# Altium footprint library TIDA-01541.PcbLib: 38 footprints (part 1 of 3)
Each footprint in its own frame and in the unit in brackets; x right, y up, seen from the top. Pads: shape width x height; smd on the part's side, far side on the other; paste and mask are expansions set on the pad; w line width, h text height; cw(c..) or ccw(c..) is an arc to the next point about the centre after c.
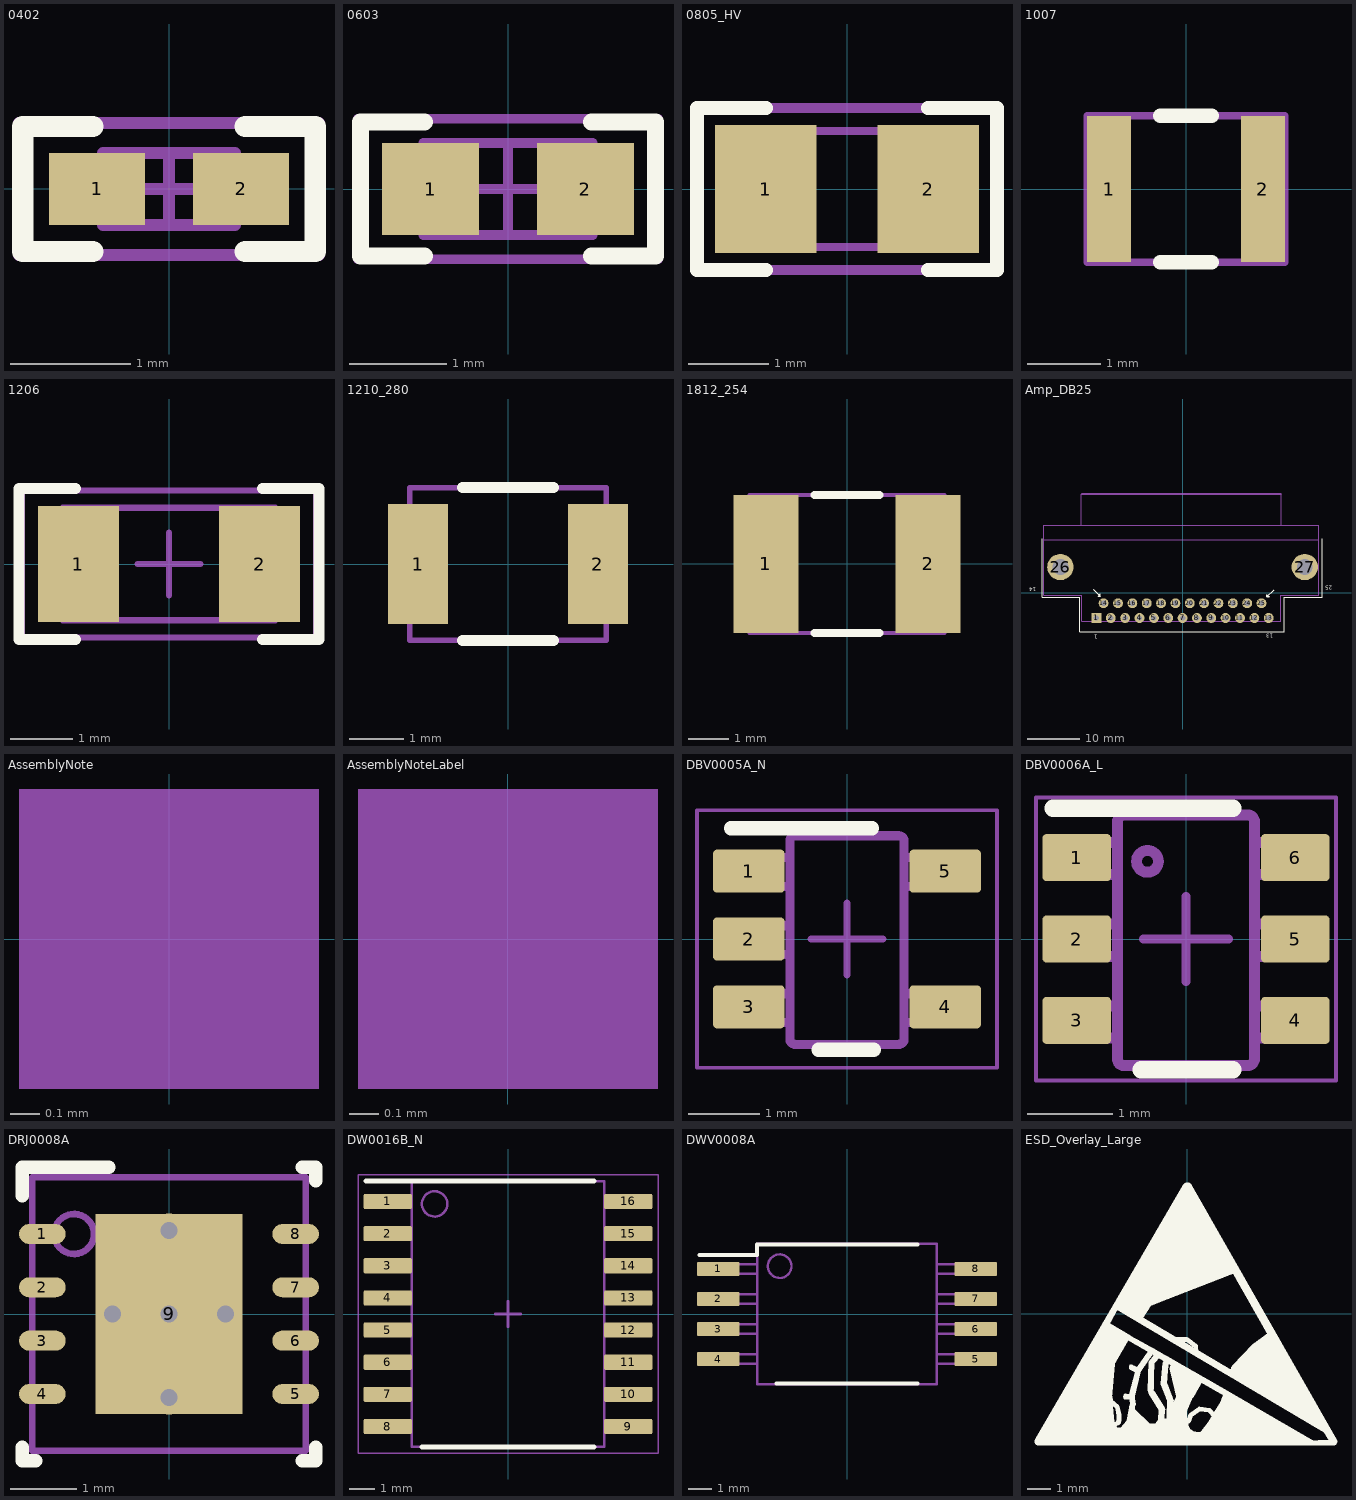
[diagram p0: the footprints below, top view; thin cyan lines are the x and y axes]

## 0402 [mm] "0402 from SM-752 data"
height 0.6
pads (2):
  rect 0.8x0.6 smd: 1(-0.6,0) 2(0.6,0)
Top Overlay:
  lines w0.178: -0.635,-0.521 -1.219,-0.521 -1.219,0.521 -0.635,0.521 ; 0.635,-0.521 1.219,-0.521 1.219,0.521 0.635,0.521
Mechanical 5:
  lines w0.1: -1.25,-0.55 -1.25,0.55 1.25,0.55 1.25,-0.55 -1.25,-0.55
  text ".Designator" at -1.6,0.305 h0.76
Mechanical 13:
  lines w0.1: -0.35,-0.3 -0.35,0.3 ; 0.35,-0.3 0.35,0.3 ; -0.55,-0.3 0.55,-0.3 0.55,0.3 -0.55,0.3 -0.55,-0.3
Mechanical 15:
  lines w0.1: -0.3,0 0.3,0 ; 0,-0.3 0,0.3 ; -1.25,-0.55 1.25,-0.55 1.25,0.55 -1.25,0.55 -1.25,-0.55
3D body: height 0.6, standoff 0, extent 0.351,-0.299 0.549,0.299
3D body: height 0.6, standoff 0, extent -0.349,-0.299 0.349,0.299
3D body: height 0.6, standoff 0, extent -0.549,-0.299 -0.351,0.299

## 0603 [mm] "0603 from SM-752 data"
height 1
pads (2):
  rect 1x0.95 smd: 1(-0.8,0) 2(0.8,0)
Top Overlay:
  lines w0.178: -0.864,-0.691 -1.524,-0.691 -1.524,0.693 -0.864,0.693 ; 0.864,-0.691 1.524,-0.691 1.524,0.693 0.864,0.693
Mechanical 5:
  lines w0.1: -1.55,-0.725 1.55,-0.725 1.55,0.725 -1.55,0.725 -1.55,-0.725
  text ".Designator" at -1.397,-0.381 h0.76
Mechanical 13:
  lines w0.1: -0.55,-0.475 -0.55,0.475 ; 0.55,-0.475 0.55,0.475 ; -0.875,-0.475 -0.875,0.475 0.875,0.475 0.875,-0.475 -0.875,-0.475
Mechanical 15:
  lines w0.1: -0.475,0 0.475,0 ; 0,-0.475 0,0.475 ; -1.55,-0.725 -1.55,0.725 1.55,0.725 1.55,-0.725 -1.55,-0.725
3D body: height 1, standoff 0, extent 0.551,-0.474 0.874,0.474
3D body: height 1, standoff 0, extent -0.549,-0.474 0.549,0.474
3D body: height 1, standoff 0, extent -0.874,-0.474 -0.551,0.474

## 0805_HV [mil] "0805 with 30mil clearance between pads"
height 57.09
pads (2):
  rect 50x63 smd: 1(-40,0) 2(40,0)
Top Overlay:
  lines w7: -40,-40 -74,-40 -74,0 -74,40 -40,40 ; 40,-40 74,-40 74,0 74,40 40,40
Mechanical 5:
  lines w5: -74,-40 74,-40 74,40 -74,40 -74,-40
  text ".Designator" at 39,13 h30
Mechanical 13:
  lines w3.94: -25.59,-28.54 -25.59,28.54 ; 25.59,-28.54 25.59,28.54 ; -43.31,-28.54 43.31,-28.54 43.31,28.54 -43.31,28.54 -43.31,-28.54
3D body: height 57.09, standoff 0, extent -43.29,-28.52 -25.61,28.52
3D body: height 57.09, standoff 0, extent -25.57,-28.52 25.57,28.52
3D body: height 57.09, standoff 0, extent 25.61,-28.52 43.29,28.52

## 1007 [mm] "SMD, 2-Leads, Body 2.5x1.8mm"
height 2
pads (2):
  rect 0.6x2 smd: 1(-1.05,0) 2(1.05,0)
Top Overlay:
  lines w0.2: -0.35,-1 0.35,-1 ; -0.35,1 0.35,1
Mechanical 5:
  lines w0.1: -1.35,-1 1.35,-1 1.35,1 -1.35,1 -1.35,-1
  text ".Designator" at -0.679,-0.229 h0.76
3D body: height 2, standoff 0, extent 0.85,-1 1.35,1
3D body: height 2, standoff 0, extent -1.35,-1 -0.85,1
3D body: height 2, standoff 0, extent -0.85,-1 0.85,1

## 1206 [mm] "1206 from SM-752 data"
height 1.35
pads (2):
  rect 1.3x1.85 smd: 1(-1.45,0) 2(1.45,0)
Top Overlay:
  lines w0.178: -1.5,-1.21 -2.4,-1.21 -2.4,1.21 -1.5,1.21 ; 1.5,-1.21 2.4,-1.21 2.4,1.21 1.5,1.21
Mechanical 5:
  lines w0.1: -1.7,-0.9 1.7,-0.9 1.7,0.9 -1.7,0.9 -1.7,-0.9
  text ".Designator" at -1.475,-0.4 h0.76
Mechanical 13:
  lines w0.1: -1.2,-0.9 -1.2,0.9 ; 1.2,-0.9 1.2,0.9 ; -1.7,-0.9 1.7,-0.9 1.7,0.9 -1.7,0.9 -1.7,-0.9
Mechanical 15:
  lines w0.1: -0.5,0 0.5,0 ; 0,-0.5 0,0.5 ; -2.35,-1.175 2.35,-1.175 2.35,1.175 -2.35,1.175 -2.35,-1.175
3D body: height 1.35, standoff 0, extent -1.699,-0.899 -1.201,0.899
3D body: height 1.35, standoff 0, extent -1.199,-0.899 1.199,0.899
3D body: height 1.35, standoff 0, extent 1.201,-0.899 1.699,0.899

## 1210_280 [mm] "SMD, 2-Leads, Body 3.6x2.8mm, Height 2.8mm"
height 2.8
pads (2):
  rect 1.1x2.2 smd: 1(-1.65,0) 2(1.65,0)
Top Overlay:
  lines w0.2: -0.835,-1.4 0.835,-1.4 ; -0.835,1.4 0.835,1.4
Mechanical 5:
  lines w0.1: -1.8,-1.4 -1.8,1.4 1.8,1.4 1.8,-1.4 -1.8,-1.4
  text ".Designator" at 0.488,-0.883 h0.76
3D body: height 2.8, standoff 0, extent -1.8,-1.4 -1.6,1.4
3D body: height 2.8, standoff 0, extent -1.6,-1.4 1.6,1.4
3D body: height 2.8, standoff 0, extent 1.6,-1.4 1.8,1.4

## 1812_254 [mm] "SMD, 2-Leads, Body 4.8x3.4mm"
height 2.54
pads (2):
  rect 1.6x3.4 smd: 1(-2,0) 2(2,0)
Top Overlay:
  lines w0.2: -0.8,-1.7 0.8,-1.7 ; -0.8,1.7 0.8,1.7
Mechanical 5:
  lines w0.1: -1.9,-1.7 -1.9,1.7 ; 1.9,-1.7 1.9,1.7 ; -2.4,-1.7 -2.4,1.7 2.4,1.7 2.4,-1.7 -2.4,-1.7
  text ".Designator" at -1.27,-0.533 h0.76
3D body: height 2.54, standoff 0, extent 1.901,-1.699 2.399,1.699
3D body: height 2.54, standoff 0, extent -1.899,-1.699 1.899,1.699
3D body: height 2.54, standoff 0, extent -2.399,-1.699 -1.901,1.699

## Amp_DB25 [mil] "Amp 5747461-1"
height 467
pads (27):
  rect 75x75 hole 41: 1(-654,-193.5)
  round 75 hole 41: 2(-545,-193.5) 3(-436,-193.5) 4(-327,-193.5) 5(-218,-193.5) 6(-109,-193.5) 7(0,-193.5) 8(109,-193.5) 9(218,-193.5) 10(327,-193.5) 11(436,-193.5) 12(545,-193.5) 13(654,-193.5) 14(-599.5,-81.5) 15(-490.5,-81.5) 16(-381.5,-81.5) 17(-272.5,-81.5) 18(-163.5,-81.5) 19(-54.5,-81.5) 20(54.5,-81.5) 21(163.5,-81.5) 22(272.5,-81.5) 23(381.5,-81.5) 24(490.5,-81.5) 25(599.5,-81.5)
  round 200 hole 120: 26(-928,193.5) 27(928,193.5)
Top Overlay:
  lines w7: -1066,406.5 -1066,-37.5 -779.5,-37.5 -779.5,-297.5 773.5,-297.5 773.5,-37.5 1060,-37.5 ; -679,26.5 -624,-28.5 ; -634.24,-20.74 -630,-22.5 ; 646,-27.5 647.76,-23.26 ; 695,21.5 640,-33.5 ; 1059,-37.5 1060,-36.5 1060,406.5 ; -624,-28.5 -624,-10.5 -642,-28.5 -624,-28.5 ; 640,-33.5 640,-15.5 658,-33.5 640,-33.5
  text "25" at 1135,52 h30
  text "14" at -1113,41 h30
  text "13" at 687,-312 h30
  text "1" at -646,-320 h30
Mechanical 5:
  lines w5: -769,510 -769,747.64 ; 749,510 749,747.64 ; -1055,400 -993,400 973,400 1035,400 ; -1055,400 -1055,375 -1055,345 -1055,-20 -795,-20 -765,-20 -765,-219 -703,-219 683,-219 745,-219 745,-20 775,-20 1035,-20 1035,345 1035,375 1035,400 ; -1055,400 -1055,510 -993,510 973,510 1035,510 1035,400 ; -769,747.64 -763.64,753 -665,753 645,753 743.64,753 749,747.64 ; -769,747.64 -665,747.64 645,747.64 749,747.64 ; -998.5,195 cw(c-936,195) -873.5,195 cw(c-936,195) -998.5,195 ; 853.5,195 ccw(c916,195) 978.5,195 ccw(c916,195) 853.5,195
  text ".Designator" at -179,207 h30
3D body "c-5747461-01-o-3d.stp": height 455, standoff -122, extent -1042.2,-220.5 1047.8,751.5

## AssemblyNote [mm] "Assembly Note"
Mechanical 5:
  rectangle: -0.508,-0.508 0.508,0.508
  text ".Comment" at 1.143,-0.508 h0.76
  text ".Designator" at -4.191,-0.508 h0.76

## AssemblyNoteLabel [mm] "Assembly Note for PCB Labels"
Mechanical 5:
  rectangle: -0.508,-0.508 0.508,0.508
  text "Install label in silkscreened box after final wash.  Text shall be 8 pt font.  Text shall be per the Label Table in the PDF schematic." at 1.143,-0.508 h0.76
  text ".Designator" at -4.191,-0.508 h0.76

## DBV0005A_N [mm] "SOT23, 5-Leads, Body 2.9x1.6mm, Pitch 0.95mm, Lead Span 2.8mm, IPC Medium Density"
height 1.45
pads (5):
  rrect17% 1x0.6 smd: 1(-1.375,0.95) 2(-1.375,0) 3(-1.375,-0.95) 4(1.375,-0.95) 5(1.375,0.95)
Top Overlay:
  lines w0.2: -1.625,1.55 0.35,1.55 ; -0.4,-1.55 0.375,-1.55
Mechanical 5:
  lines w0.127: -0.801,1.371 cw(c-0.725,1.37) -0.725,1.446 ; -0.801,1.37 -0.801,-1.399 -0.801,-1.4 ccw(c-0.725,-1.399) -0.725,-1.475 ; -0.801,1.37 -0.801,1.371 ; -0.725,-1.475 -0.725,-1.475 ; -0.725,-1.475 0.723,-1.475 0.724,-1.475 ccw(c0.723,-1.399) 0.799,-1.4 0.799,-1.399 0.799,1.37 ; -0.725,1.446 0.723,1.446 0.724,1.446 cw(c0.723,1.37) 0.799,1.371 ; -0.725,1.446 -0.725,1.446 ; 0.799,1.37 0.799,1.371 ; -1.423,-1.167 -1.199,-1.167 -1.105,-1.167 -1.088,-1.167 -0.835,-1.167 -0.801,-1.167 -0.801,-0.767 -0.835,-0.767 -1.088,-0.767 -1.105,-0.767 -1.199,-0.767 -1.423,-0.767 -1.423,-1.167 ; -1.423,-0.215 -1.199,-0.215 -1.105,-0.215 -1.088,-0.215 -0.835,-0.215 -0.801,-0.215 -0.801,0.186 -0.835,0.186 -1.088,0.186 -1.105,0.186 -1.199,0.186 -1.423,0.186 -1.423,-0.215 ; -1.423,0.738 -1.199,0.738 -1.105,0.738 -1.088,0.738 -0.835,0.738 -0.801,0.738 -0.801,1.138 -0.835,1.138 -1.088,1.138 -1.105,1.138 -1.199,1.138 -1.423,1.138 -1.423,0.738 ; 0.799,-1.167 0.799,-0.767 0.834,-0.767 1.087,-0.767 1.103,-0.767 1.198,-0.767 1.422,-0.767 1.422,-1.167 1.198,-1.167 1.103,-1.167 1.087,-1.167 0.834,-1.167 0.799,-1.167 ; 0.799,0.738 0.799,1.138 0.834,1.138 1.087,1.138 1.103,1.138 1.198,1.138 1.422,1.138 1.422,0.738 1.198,0.738 1.103,0.738 1.087,0.738 0.834,0.738 0.799,0.738
  text ".Designator" at 0.432,-0.838 h0.76
Mechanical 15:
  lines w0.05: -2.1,-1.8 2.1,-1.8 2.1,1.8 -2.1,1.8 -2.1,-1.8
  lines w0.1: -0.5,0 0.5,0 ; 0,-0.5 0,0.5
3D body "DBV0005A.stp": height 1.09, standoff 0, extent -1.422,-1.461 1.423,1.46

## DBV0006A_L [mm] "SOT23, 6-Leads, Body 2.9x1.6mm, Pitch 0.95mm, Lead Span 2.8mm, IPC High Density"
height 1.45
pads (6):
  rrect18% 0.8x0.55 smd: 1(-1.275,0.95) 2(-1.275,0) 3(-1.275,-0.95) 4(1.275,-0.95) 5(1.275,0) 6(1.275,0.95)
Top Overlay:
  lines w0.2: -1.55,1.525 0.55,1.525 ; -0.525,-1.525 0.55,-1.525
Mechanical 5:
  lines w0.127: 0.724,-1.475 ccw(c0.723,-1.399) 0.8,-1.399 0.8,1.37 ccw(c0.723,1.37) 0.724,1.446 ; 0.723,-1.475 0.724,-1.475 ; 0.723,-1.475 -0.724,-1.475 -0.725,-1.475 cw(c-0.724,-1.399) -0.801,-1.399 -0.801,1.37 cw(c-0.724,1.37) -0.725,1.446 -0.724,1.446 0.723,1.446 ; 0.723,1.446 0.724,1.446 ; -1.423,-1.154 -1.206,-1.154 -1.113,-1.154 -1.081,-1.154 -0.828,-1.154 -0.801,-1.154 -0.801,-0.78 -0.828,-0.78 -1.081,-0.78 -1.113,-0.78 -1.206,-0.78 -1.423,-0.78 -1.423,-1.154 ; -1.423,-0.202 -1.206,-0.202 -1.113,-0.202 -1.081,-0.202 -0.828,-0.202 -0.801,-0.202 -0.801,0.173 -0.828,0.173 -1.081,0.173 -1.113,0.173 -1.206,0.173 -1.423,0.173 -1.423,-0.202 ; -1.423,0.751 -1.206,0.751 -1.113,0.751 -1.081,0.751 -0.828,0.751 -0.801,0.751 -0.801,1.125 -0.828,1.125 -1.081,1.125 -1.113,1.125 -1.206,1.125 -1.423,1.125 -1.423,0.751 ; -0.577,0.906 cw(c-0.45,0.906) -0.323,0.906 cw(c-0.45,0.906) -0.577,0.906 ; 0.8,-1.154 0.827,-1.154 1.08,-1.154 1.112,-1.154 1.205,-1.154 1.422,-1.154 1.422,-0.78 1.205,-0.78 1.112,-0.78 1.08,-0.78 0.827,-0.78 0.8,-0.78 0.8,-1.154 ; 0.8,-0.202 0.827,-0.202 1.08,-0.202 1.112,-0.202 1.205,-0.202 1.422,-0.202 1.422,0.173 1.205,0.173 1.112,0.173 1.08,0.173 0.827,0.173 0.8,0.173 0.8,-0.202 ; 0.8,0.751 0.827,0.751 1.08,0.751 1.112,0.751 1.205,0.751 1.422,0.751 1.422,1.125 1.205,1.125 1.112,1.125 1.08,1.125 0.827,1.125 0.8,1.125 0.8,0.751
  text ".Designator" at -0.229,0.432 h0.76
Mechanical 15:
  lines w0.05: -1.75,-1.65 1.75,-1.65 1.75,1.65 -1.75,1.65 -1.75,-1.65
  lines w0.1: -0.5,0 0.5,0 ; 0,-0.5 0,0.5
3D body "DBV0006A.stp": height 1.12, standoff 0, extent -1.422,-1.461 1.423,1.46

## DRJ0008A [mm] "SON, 8-Leads, Body 4x4mm, Pitch 0.8mm, Thermal Pad 3x2.2mm, TI Recommended"
height 0.8
pads (9):
  oval 0.7x0.3 smd: 1(-1.9,1.2) 2(-1.9,0.4) 3(-1.9,-0.4) 4(-1.9,-1.2) 5(1.9,-1.2) 6(1.9,-0.4) 7(1.9,0.4) 8(1.9,1.2)
  rect 2.2x3 smd paste-1.1: 9(0,0)
via 0.85,0 diameter 0.508 hole 0.254
via 0,0 diameter 0.508 hole 0.254
via 0,1.25 diameter 0.508 hole 0.254
via 0,-1.25 diameter 0.508 hole 0.254
via -0.85,0 diameter 0.508 hole 0.254
Top Overlay:
  lines w0.2: -2.2,-2 -2.2,-2.2 -2,-2.2 ; -2.2,1.775 -2.2,2.2 -0.9,2.2 ; 2,-2.2 2.2,-2.2 2.2,-2 ; 2,2.2 2.2,2.2 2.2,2
Top Paste:
  rectangle: 0.1,0.1 1.081,1.41
  region: -0.1,1.41 -1.081,1.41 -1.081,0.1 -0.1,0.1
  region: -0.1,-0.1 -1.081,-0.1 -1.081,-1.41 -0.1,-1.41
  rectangle: 0.1,-1.41 1.081,-0.1
Mechanical 5:
  circle w0.1: c-1.425,1.2 r0.3
  lines w0.1: -2.05,-2.05 2.05,-2.05 2.05,2.05 -2.05,2.05 -2.05,-2.05
  text ".Designator" at -0.711,-0.559 h0.76
3D body: height 0.8, standoff 0, extent -2.05,-2.05 2.05,2.05
3D body: height 0.81, standoff 0.5, extent -1.724,0.901 -1.126,1.499

## DW0016B_N [mm] "SOIC, 16-Leads, Body 10.5x7.6mm, Pitch 1.27mm, IPC Medium Density"
height 2.65
pads (16):
  rrect17% 1.9x0.6 smd: 1(-4.75,4.445) 2(-4.75,3.175) 3(-4.75,1.905) 4(-4.75,0.635) 5(-4.75,-0.635) 6(-4.75,-1.905) 7(-4.75,-3.175) 8(-4.75,-4.445) 9(4.75,-4.445) 10(4.75,-3.175) 11(4.75,-1.905) 12(4.75,-0.635) 13(4.75,0.635) 14(4.75,1.905) 15(4.75,3.175) 16(4.75,4.445)
Top Overlay:
  lines w0.2: -5.6,5.25 3.4,5.25 ; -3.4,-5.25 3.4,-5.25
Mechanical 5:
  text ".Designator" at -0.406,1.346 h0.76
Mechanical 13:
  circle w0.1: c-2.9,4.35 r0.5
  lines w0.1: -3.8,-5.25 3.8,-5.25 3.8,5.25 -3.8,5.25 -3.8,-5.25
Mechanical 15:
  lines w0.05: -5.925,-5.5 5.925,-5.5 5.925,5.5 -5.925,5.5 -5.925,-5.5
  lines w0.1: -0.5,0 0.5,0 ; 0,-0.5 0,0.5
3D body "DW0016B.stp": height 2.59, standoff 0, extent -5.167,-5.15 5.167,5.15

## DWV0008A [mm] "SOIC, 8-Leads, Body 5.95x7.6mm (max), Pitch 1.27mm"
height 2.8
pads (8):
  rrect17% 1.8x0.6 smd: 1(-5.45,1.905) 2(-5.45,0.635) 3(-5.45,-0.635) 4(-5.45,-1.905) 5(5.45,-1.905) 6(5.45,-0.635) 7(5.45,0.635) 8(5.45,1.905)
Top Overlay:
  lines w0.17: -6.25,2.5 -3.8,2.5 -3.8,2.95 2.975,2.95 ; -2.975,-2.95 2.975,-2.95
Mechanical 5:
  circle w0.1: c-2.85,2.025 r0.5
  lines w0.1: -3.805,-2.105 -5.8,-2.105 -5.8,-1.705 -3.805,-1.705 ; -3.805,-0.835 -5.8,-0.835 -5.8,-0.435 -3.805,-0.435 ; -3.805,0.435 -5.8,0.435 -5.8,0.835 -3.805,0.835 ; -3.805,1.705 -5.8,1.705 -5.8,2.105 -3.805,2.105 ; 3.805,-2.105 5.8,-2.105 5.8,-1.705 3.805,-1.705 ; 3.805,-0.835 5.8,-0.835 5.8,-0.435 3.805,-0.435 ; 3.805,0.435 5.8,0.435 5.8,0.835 3.805,0.835 ; 3.805,1.705 5.8,1.705 5.8,2.105 3.805,2.105 ; -3.8,-2.975 3.8,-2.975 3.8,2.975 -3.8,2.975 -3.8,-2.975
  text ".Designator" at 0.102,-0.762 h0.76
3D body "DWV0008A.stp": height 2.67, standoff -0.03, extent -5.768,-2.925 5.768,2.925

## ESD_Overlay_Large [mm]
Top Overlay:
  drawing of 13628 lines, arcs and shapes, not listed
